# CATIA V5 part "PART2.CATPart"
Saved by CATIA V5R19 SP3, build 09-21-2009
Part number: PART2
Bounding box of the stored display mesh (mm): x 0 to 33, y -150 to 150, z -149.95 to 149.95
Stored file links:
  C:\Documents and Settings\Frielingsdorf\Desktop\PART2.CATPart
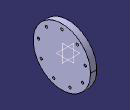
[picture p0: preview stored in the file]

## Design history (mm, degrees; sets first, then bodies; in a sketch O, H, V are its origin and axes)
Body1 (main body)
  Sketch1 on yz-plane, origin (0, 0, 0), H (0, 1, 0), V (0, 0, 1)
    circle A1 centre (0, 0) radius 150
    radius A1 = 150
  Pad1: profile Sketch1, direction (1, 0, 0), length 33
  Sketch2 on end face of Pad1, origin (33, 0, 0), H (0, 1, 0), V (0, 0, 1)
    point P1 (0, 125)
    reference intersected line E1 through (0, 0) direction (0, 1) from zx-plane
    distance H P1 = 125
    coincidence: P1 E1
  Hole1: placed by Sketch2, at (33, 0, 125) direction (-1, 0, 0), diameter 12.5, through (limit type 6)
  CircPattern1: of Hole1, instances 9, angular step 40 {= 360.0*1 deg/CircPattern1.AngularNumber}, axis from X axis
